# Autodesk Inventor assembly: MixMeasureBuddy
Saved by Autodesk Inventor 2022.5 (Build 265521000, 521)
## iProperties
Created: 2024-05
Part Number: MixMeasureBuddy
Document SubType Name: Assembly
Designer: AdminForWorker
Title: MixMeasureBuddy v69
Author: AdminForWorker
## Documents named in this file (2)
- c:\worker\convert-fusion-r02-cosv3\tmp\job-1\117\temp\files\6ec14fa5-d006-4685-9aed-7a0566dc038b\df9dc0c0-920a-4331-97ce-e28dfca48497.iam
- c:\worker\convert-fusion-r02-cosv3\tmp\job-1\117\temp\files\6ec14fa5-d006-4685-9aed-7a0566dc038b\cellplate.ipt
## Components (1 placed, 1 different names)
1. cellplate:1
